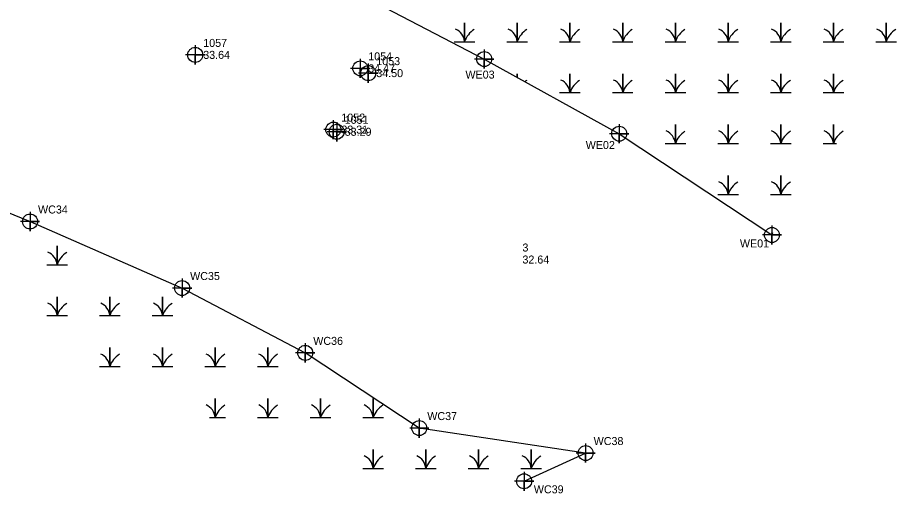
# Model space of a CAD drawing. Extents: x 2138832 to 2141061, y 149156 to 150675.
# Drawn here: x 2140787 to 2141061.5, y 149156 to 149304.7 of the extents above; entities that cross this region are included whole.
import ezdxf

# ---------------------------------------------------------------- set-up
doc = ezdxf.new("R2010")
doc.units = 0
for name, color, linetype in [('CTL Secondary Horizontal and Vertical Cogo Elevation', 7, 'Continuous'), ('CTL Secondary Horizontal and Vertical Cogo Number', 7, 'Continuous'), ('Exist Environmental Wetland Boundary', 7, 'Continuous'), ('Exist Environmental Wetland Boundary Cogo Number', 7, 'Continuous'), ('Exist Environmental Wetland Boundary Cogo Point CELL', 7, 'Continuous'), ('Exist Roads EOP Cogo Elevation', 7, 'Continuous'), ('Exist Roads EOP Cogo Number', 7, 'Continuous'), ('Exist Roads EOP Cogo Point CELL', 7, 'Continuous')]:
    doc.layers.add(name, color=color, linetype=linetype)

msp = doc.modelspace()

# ---------------------------------------------------------------- linework, layer by layer
at = {"layer": 'Exist Environmental Wetland Boundary'}
for points in [[(2140626.92, 149434.6), (2140640.09, 149441.77), (2140665.85, 149433.31), (2140691.67, 149415.77), (2140722.53, 149397.21), (2140775.79, 149382.91), (2140815.44, 149353.55), (2140873.49, 149322.65), (2140932.75, 149291.76), (2140974.9, 149268.42), (2141022.6, 149236.76)], [(2140718.2, 149267.79), (2140725.81, 149266.3), (2140752.89, 149265.52), (2140761.69, 149250.68), (2140772.72, 149248.34), (2140790.93, 149240.98), (2140838.41, 149220.19), (2140876.86, 149199.92)], [(2140945.2, 149159.79), (2140964.42, 149168.61), (2140912.47, 149176.42), (2140876.86, 149199.92)]]:
    msp.add_lwpolyline(points, dxfattribs=at)
at = {"layer": 'Exist Environmental Wetland Boundary Cogo Point CELL'}
for p, q in [((2140963.88, 149168.36), (2140963.88, 149168.69)), ((2140963.88, 149168.69), (2140963.88, 149168.36))]:
    msp.add_line(p, q, dxfattribs=at)
for points in [[(2140923.4, 149297.18), (2140926.62, 149297.18), (2140926.62, 149303.1), (2140926.62, 149297.18), (2140929.85, 149297.18)], [(2140939.85, 149297.18), (2140943.07, 149297.18), (2140943.07, 149303.1), (2140943.07, 149297.18), (2140946.3, 149297.18)], [(2140956.3, 149297.18), (2140959.52, 149297.18), (2140959.52, 149303.1), (2140959.52, 149297.18), (2140962.75, 149297.18)], [(2140972.75, 149297.18), (2140975.98, 149297.18), (2140975.98, 149303.1), (2140975.98, 149297.18), (2140979.2, 149297.18)], [(2140989.2, 149297.18), (2140992.43, 149297.18), (2140992.43, 149303.1), (2140992.43, 149297.18), (2140995.65, 149297.18)], [(2141005.65, 149297.18), (2141008.88, 149297.18), (2141008.88, 149303.1), (2141008.88, 149297.18), (2141012.1, 149297.18)], [(2141022.1, 149297.18), (2141025.33, 149297.18), (2141025.33, 149303.1), (2141025.33, 149297.18), (2141028.55, 149297.18)], [(2141038.55, 149297.18), (2141041.78, 149297.18), (2141041.78, 149303.1), (2141041.78, 149297.18), (2141045.01, 149297.18)], [(2141055.01, 149297.18), (2141058.23, 149297.18), (2141058.23, 149303.1), (2141058.23, 149297.18), (2141061.46, 149297.18)], [(2140932.75, 149294.76), (2140932.75, 149288.76), (2140932.75, 149291.76), (2140935.75, 149291.76), (2140929.75, 149291.76)], [(2140943.07, 149286.04), (2140943.07, 149287.18), (2140943.07, 149286.04)], [(2140956.3, 149281.26), (2140959.52, 149281.26), (2140959.52, 149287.18), (2140959.52, 149281.26), (2140962.75, 149281.26)], [(2140972.75, 149281.26), (2140975.98, 149281.26), (2140975.98, 149287.18), (2140975.98, 149281.26), (2140979.2, 149281.26)], [(2140989.2, 149281.26), (2140992.43, 149281.26), (2140992.43, 149287.18), (2140992.43, 149281.26), (2140995.65, 149281.26)], [(2141005.65, 149281.26), (2141008.88, 149281.26), (2141008.88, 149287.18), (2141008.88, 149281.26), (2141012.1, 149281.26)], [(2141022.1, 149281.26), (2141025.33, 149281.26), (2141025.33, 149287.18), (2141025.33, 149281.26), (2141028.55, 149281.26)], [(2141038.55, 149281.26), (2141041.78, 149281.26), (2141041.78, 149287.18), (2141041.78, 149281.26), (2141045.01, 149281.26)], [(2140974.9, 149271.42), (2140974.9, 149265.42), (2140974.9, 149268.42), (2140977.9, 149268.42), (2140971.9, 149268.42)], [(2140989.2, 149265.35), (2140992.43, 149265.35), (2140992.43, 149271.26), (2140992.43, 149265.35), (2140995.65, 149265.35)], [(2141005.65, 149265.35), (2141008.88, 149265.35), (2141008.88, 149271.26), (2141008.88, 149265.35), (2141012.1, 149265.35)], [(2141022.1, 149265.35), (2141025.33, 149265.35), (2141025.33, 149271.26), (2141025.33, 149265.35), (2141028.55, 149265.35)], [(2141038.55, 149265.35), (2141041.78, 149265.35), (2141041.78, 149271.26), (2141041.78, 149265.35), (2141042.71, 149265.35)], [(2141005.65, 149249.43), (2141008.88, 149249.43), (2141008.88, 149255.35), (2141008.88, 149249.43), (2141012.1, 149249.43)], [(2141022.1, 149249.43), (2141025.33, 149249.43), (2141025.33, 149255.35), (2141025.33, 149249.43), (2141028.55, 149249.43)], [(2140790.93, 149243.98), (2140790.93, 149237.98), (2140790.93, 149240.98), (2140793.93, 149240.98), (2140787.93, 149240.98)], [(2141022.6, 149239.76), (2141022.6, 149233.76), (2141022.6, 149236.76), (2141025.6, 149236.76), (2141019.6, 149236.76)], [(2140796.14, 149227.47), (2140799.36, 149227.47), (2140799.36, 149233.39), (2140799.36, 149227.47), (2140802.59, 149227.47)], [(2140838.41, 149223.19), (2140838.41, 149217.19), (2140838.41, 149220.19), (2140841.41, 149220.19), (2140835.41, 149220.19)], [(2140796.14, 149211.55), (2140799.36, 149211.55), (2140799.36, 149217.47), (2140799.36, 149211.55), (2140802.59, 149211.55)], [(2140812.59, 149211.55), (2140815.82, 149211.55), (2140815.82, 149217.47), (2140815.82, 149211.55), (2140819.04, 149211.55)], [(2140829.04, 149211.55), (2140832.27, 149211.55), (2140832.27, 149217.47), (2140832.27, 149211.55), (2140835.49, 149211.55)], [(2140812.59, 149195.63), (2140815.82, 149195.63), (2140815.82, 149201.55), (2140815.82, 149195.63), (2140819.04, 149195.63)], [(2140829.04, 149195.63), (2140832.27, 149195.63), (2140832.27, 149201.55), (2140832.27, 149195.63), (2140835.49, 149195.63)], [(2140845.49, 149195.63), (2140848.72, 149195.63), (2140848.72, 149201.55), (2140848.72, 149195.63), (2140851.94, 149195.63)], [(2140861.94, 149195.63), (2140865.17, 149195.63), (2140865.17, 149201.55), (2140865.17, 149195.63), (2140868.4, 149195.63)], [(2140876.86, 149202.92), (2140876.86, 149196.92), (2140876.86, 149199.92), (2140879.86, 149199.92), (2140873.86, 149199.92)], [(2140846.97, 149179.72), (2140848.72, 149179.72), (2140848.72, 149185.63), (2140848.72, 149179.72), (2140851.94, 149179.72)], [(2140861.94, 149179.72), (2140865.17, 149179.72), (2140865.17, 149185.63), (2140865.17, 149179.72), (2140868.4, 149179.72)], [(2140878.4, 149179.72), (2140881.62, 149179.72), (2140881.62, 149185.63), (2140881.62, 149179.72), (2140884.85, 149179.72)], [(2140894.85, 149179.72), (2140898.07, 149179.72), (2140898.07, 149185.63), (2140898.07, 149179.72), (2140901.3, 149179.72)], [(2140912.47, 149179.42), (2140912.47, 149173.42), (2140912.47, 149176.42), (2140915.47, 149176.42), (2140909.47, 149176.42)], [(2140964.42, 149171.61), (2140964.42, 149165.61), (2140964.42, 149168.61), (2140967.42, 149168.61), (2140961.42, 149168.61)], [(2140894.85, 149163.8), (2140898.07, 149163.8), (2140898.07, 149169.72), (2140898.07, 149163.8), (2140901.3, 149163.8)], [(2140911.3, 149163.8), (2140914.52, 149163.8), (2140914.52, 149169.72), (2140914.52, 149163.8), (2140917.75, 149163.8)], [(2140927.75, 149163.8), (2140930.97, 149163.8), (2140930.97, 149169.72), (2140930.97, 149163.8), (2140934.2, 149163.8)], [(2140944.2, 149163.8), (2140947.43, 149163.8), (2140947.43, 149169.72), (2140947.43, 149163.8), (2140950.65, 149163.8)], [(2140945.2, 149162.79), (2140945.2, 149156.79), (2140945.2, 149159.79), (2140948.2, 149159.79), (2140942.2, 149159.79)]]:
    msp.add_lwpolyline(points, dxfattribs=at)
for centre in [(2140932.75, 149291.76), (2140974.9, 149268.42), (2140790.93, 149240.98), (2141022.6, 149236.76), (2140838.41, 149220.19), (2140876.86, 149199.92), (2140912.47, 149176.42), (2140964.42, 149168.61), (2140945.2, 149159.79)]:
    msp.add_circle(centre, 2.34, dxfattribs=at)
for centre, radius, start, end in [((2140922.02, 149296.85), 4.61, 4.1403, 67.535), ((2140933.46, 149294.91), 7.21, 122.1274, 161.6222), ((2140938.47, 149296.85), 4.61, 4.1403, 67.535), ((2140949.91, 149294.91), 7.21, 122.1274, 161.6222), ((2140954.92, 149296.85), 4.61, 4.1403, 67.535), ((2140966.37, 149294.91), 7.21, 122.1274, 161.6222), ((2140971.38, 149296.85), 4.61, 4.1403, 67.535), ((2140982.82, 149294.91), 7.21, 122.1274, 161.6222), ((2140987.83, 149296.85), 4.61, 4.1403, 67.535), ((2140999.27, 149294.91), 7.21, 122.1274, 161.6222), ((2141004.28, 149296.85), 4.61, 4.1403, 67.535), ((2141015.72, 149294.91), 7.21, 122.1274, 161.6222), ((2141020.73, 149296.85), 4.61, 4.1403, 67.535), ((2141032.17, 149294.91), 7.21, 122.1274, 161.6222), ((2141037.18, 149296.85), 4.61, 4.1403, 67.535), ((2141048.62, 149294.91), 7.21, 122.1274, 161.6222), ((2141053.63, 149296.85), 4.61, 4.1403, 67.535), ((2141065.07, 149294.91), 7.21, 122.1274, 161.6222), ((2140949.91, 149278.99), 7.21, 122.1274, 127.6944), ((2140954.92, 149280.93), 4.61, 4.1403, 67.535), ((2140966.37, 149278.99), 7.21, 122.1274, 161.6222), ((2140971.38, 149280.93), 4.61, 4.1403, 67.535), ((2140982.82, 149278.99), 7.21, 122.1274, 161.6222), ((2140987.83, 149280.93), 4.61, 4.1403, 67.535), ((2140999.27, 149278.99), 7.21, 122.1274, 161.6222), ((2141004.28, 149280.93), 4.61, 4.1403, 67.535), ((2141015.72, 149278.99), 7.21, 122.1274, 161.6222), ((2141020.73, 149280.93), 4.61, 4.1403, 67.535), ((2141032.17, 149278.99), 7.21, 122.1274, 161.6222), ((2141037.18, 149280.93), 4.61, 4.1403, 67.535), ((2141048.62, 149278.99), 7.21, 122.1274, 161.6222), ((2140987.83, 149265.01), 4.61, 4.1403, 67.535), ((2140999.27, 149263.07), 7.21, 122.1274, 161.6222), ((2141004.28, 149265.01), 4.61, 4.1403, 67.535), ((2141015.72, 149263.07), 7.21, 122.1274, 161.6222), ((2141020.73, 149265.01), 4.61, 4.1403, 67.535), ((2141032.17, 149263.07), 7.21, 122.1274, 161.6222), ((2141037.18, 149265.01), 4.61, 4.1403, 67.535), ((2141048.62, 149263.07), 7.21, 122.1274, 161.6222), ((2141004.28, 149249.1), 4.61, 4.1403, 67.535), ((2141015.72, 149247.16), 7.21, 122.1274, 161.6222), ((2141020.73, 149249.1), 4.61, 4.1403, 67.535), ((2141032.17, 149247.16), 7.21, 122.1274, 161.6222), ((2141020.73, 149233.18), 4.61, 61.3962, 67.535), ((2140794.76, 149227.14), 4.61, 4.1403, 67.535), ((2140806.21, 149225.2), 7.21, 122.1274, 161.6222), ((2140794.76, 149211.22), 4.61, 4.1403, 67.535), ((2140806.21, 149209.28), 7.21, 122.1274, 161.6222), ((2140811.22, 149211.22), 4.61, 4.1403, 67.535), ((2140822.66, 149209.28), 7.21, 122.1274, 161.6222), ((2140827.67, 149211.22), 4.61, 4.1403, 67.535), ((2140839.11, 149209.28), 7.21, 122.1274, 161.6222), ((2140811.22, 149195.3), 4.61, 4.1403, 67.535), ((2140822.66, 149193.36), 7.21, 122.1274, 161.6222), ((2140827.67, 149195.3), 4.61, 4.1403, 67.535), ((2140839.11, 149193.36), 7.21, 122.1274, 161.6222), ((2140844.12, 149195.3), 4.61, 4.1403, 67.535), ((2140855.56, 149193.36), 7.21, 122.1274, 161.6222), ((2140860.57, 149195.3), 4.61, 4.1403, 67.535), ((2140872.01, 149193.36), 7.21, 122.1274, 161.6222), ((2140844.12, 149179.38), 4.61, 4.1403, 67.535), ((2140855.56, 149177.44), 7.21, 122.1274, 161.6222), ((2140860.57, 149179.38), 4.61, 4.1403, 67.535), ((2140872.01, 149177.44), 7.21, 122.1274, 161.6222), ((2140877.02, 149179.38), 4.61, 4.1403, 67.535), ((2140888.46, 149177.44), 7.21, 122.1274, 161.6222), ((2140893.47, 149179.38), 4.61, 4.1403, 67.535), ((2140904.91, 149177.44), 7.21, 122.1274, 161.6222), ((2140893.47, 149163.47), 4.61, 4.1403, 67.535), ((2140904.91, 149161.53), 7.21, 122.1274, 161.6222), ((2140909.92, 149163.47), 4.61, 4.1403, 67.535), ((2140921.36, 149161.53), 7.21, 122.1274, 161.6222), ((2140926.37, 149163.47), 4.61, 4.1403, 67.535), ((2140937.82, 149161.53), 7.21, 122.1274, 161.6222), ((2140942.83, 149163.47), 4.61, 4.1403, 67.535), ((2140954.27, 149161.53), 7.21, 122.1274, 161.6222)]:
    msp.add_arc(centre, radius, start, end, dxfattribs=at)
at = {"layer": 'Exist Roads EOP Cogo Point CELL'}
for points in [[(2140842.51, 149296.05), (2140842.51, 149290.05), (2140842.51, 149293.05), (2140845.51, 149293.05), (2140839.51, 149293.05)], [(2140894.04, 149291.84), (2140894.04, 149285.84), (2140894.04, 149288.84), (2140897.04, 149288.84), (2140891.04, 149288.84)], [(2140896.54, 149290.35), (2140896.54, 149284.35), (2140896.54, 149287.35), (2140899.54, 149287.35), (2140893.54, 149287.35)], [(2140885.63, 149272.7), (2140885.63, 149266.7), (2140885.63, 149269.7), (2140888.63, 149269.7), (2140882.63, 149269.7)], [(2140886.68, 149272.02), (2140886.68, 149266.02), (2140886.68, 149269.02), (2140889.68, 149269.02), (2140883.68, 149269.02)]]:
    msp.add_lwpolyline(points, dxfattribs=at)
for centre in [(2140842.51, 149293.05), (2140894.04, 149288.84), (2140896.54, 149287.35), (2140885.63, 149269.7), (2140886.68, 149269.02)]:
    msp.add_circle(centre, 2.34, dxfattribs=at)

# ---------------------------------------------------------------- texts
at = {"layer": 'CTL Secondary Horizontal and Vertical Cogo Elevation'}
msp.add_text('32.64', height=2.5, dxfattribs=at).set_placement((2140944.68, 149227.84))
at = {"layer": 'CTL Secondary Horizontal and Vertical Cogo Number'}
msp.add_text('3', height=2.5, dxfattribs=at).set_placement((2140944.68, 149231.59))
at = {"layer": 'Exist Environmental Wetland Boundary Cogo Number'}
for s, p in [('WE03', (2140926.88, 149285.64)), ('WE02', (2140964.44, 149263.63)), ('WC34', (2140793.43, 149243.48)), ('WE01', (2141012.59, 149232.88)), ('WC35', (2140840.91, 149222.69)), ('WC36', (2140879.36, 149202.42)), ('WC37', (2140914.97, 149178.92)), ('WC38', (2140966.92, 149171.11)), ('WC39', (2140948.24, 149156.03))]:
    msp.add_text(s, height=2.5, dxfattribs=at).set_placement(p)
at = {"layer": 'Exist Roads EOP Cogo Elevation'}
for s, p in [('33.64', (2140845.01, 149291.8)), ('34.47', (2140896.54, 149287.59)), ('34.50', (2140899.04, 149286.1)), ('33.31', (2140888.13, 149268.45)), ('33.29', (2140889.18, 149267.77))]:
    msp.add_text(s, height=2.5, dxfattribs=at).set_placement(p)
at = {"layer": 'Exist Roads EOP Cogo Number'}
for s, p in [('1057', (2140845.01, 149295.55)), ('1054', (2140896.54, 149291.34)), ('1053', (2140899.04, 149289.85)), ('1052', (2140888.13, 149272.2)), ('1051', (2140889.18, 149271.52))]:
    msp.add_text(s, height=2.5, dxfattribs=at).set_placement(p)

doc.saveas('drawing.dxf')
